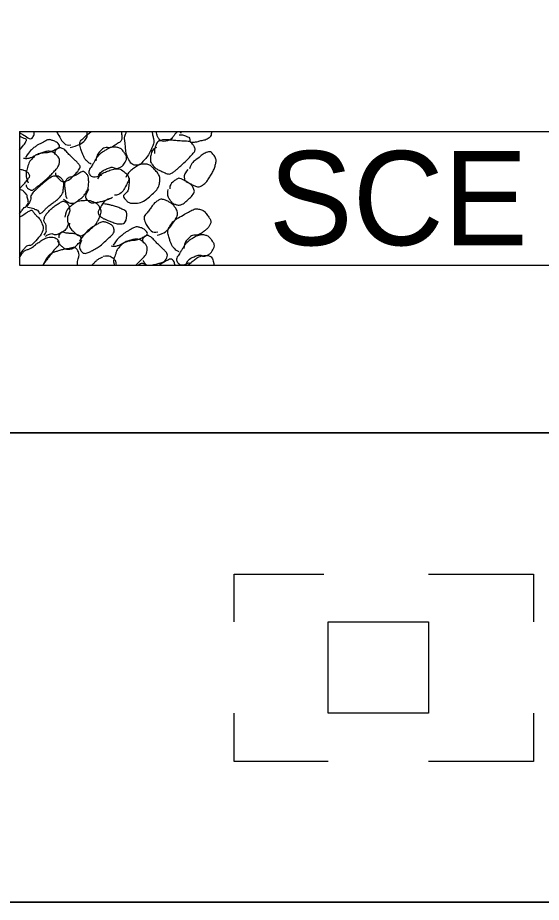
# Model space of a CAD drawing. Extents: x 1.3 to 34, y 0 to 22.5.
# Drawn here: x 11.694 to 12.252, y 7.825 to 8.767 of the extents above; entities that cross this region are included whole.
import ezdxf

# ---------------------------------------------------------------- set-up
doc = ezdxf.new("R2010")
doc.units = 0
for name, color, linetype in [('ANNO-SYMB', 7, 'Continuous'), ('ANNO-TABL', 7, 'Continuous'), ('USER-LINE', 7, 'Continuous')]:
    doc.layers.add(name, color=color, linetype=linetype)

msp = doc.modelspace()

# ---------------------------------------------------------------- linework, layer by layer
at = {"layer": 'ANNO-SYMB'}
for p, q in [((11.69643, 8.64567), (11.69641, 8.50339)), ((11.69643, 8.64567), (11.9385, 8.64567)), ((11.9385, 8.64567), (12.27755, 8.64567)), ((11.69641, 8.50339), (11.9385, 8.50338)), ((11.9385, 8.50338), (12.26197, 8.50339))]:
    msp.add_line(p, q, dxfattribs=at)
for points in [[(11.9252, 8.12358), (11.9252, 8.17447), (12.02037, 8.17447)], [(12.13208, 8.17447), (12.24378, 8.17447), (12.24378, 8.12358)], [(12.025, 7.97486), (11.9252, 7.97486), (11.9252, 8.02642)], [(12.24378, 8.02642), (12.24378, 7.97486), (12.13208, 7.97486)]]:
    msp.add_lwpolyline(points, dxfattribs=at)
msp.add_lwpolyline([(12.025, 8.12358), (12.13208, 8.12358), (12.13208, 8.02642), (12.025, 8.02642)], close=True, dxfattribs=at)
for points, degree in [([(11.69643, 8.64425), (11.6969, 8.64401), (11.69737, 8.64377), (11.69784, 8.64354), (11.70193, 8.64147), (11.7089, 8.63644), (11.71129, 8.6407), (11.71216, 8.64226), (11.7117, 8.64403), (11.71198, 8.64567)], 3), ([(11.69643, 8.62585), (11.6987, 8.62918), (11.70228, 8.63257), (11.7035, 8.63575), (11.70437, 8.63801), (11.69854, 8.63898), (11.69643, 8.64072)], 3), ([(11.70066, 8.61735), (11.70251, 8.61701), (11.7045, 8.6169), (11.70634, 8.61735), (11.70983, 8.61821), (11.71289, 8.62044), (11.71624, 8.62159), (11.72169, 8.62346), (11.72761, 8.62299), (11.73323, 8.62585), (11.73565, 8.62707), (11.7395, 8.62923), (11.7389, 8.6308), (11.73808, 8.63292), (11.73365, 8.63546), (11.7304, 8.63646), (11.72713, 8.63748), (11.72367, 8.63518), (11.7205, 8.63363), (11.71747, 8.63216), (11.71465, 8.63081), (11.712, 8.62868), (11.70822, 8.62563), (11.70516, 8.62224), (11.70279, 8.61806)], 3), ([(11.73605, 8.64567), (11.73597, 8.64545), (11.73593, 8.64519), (11.73607, 8.64496), (11.73989, 8.63849), (11.74502, 8.63009), (11.75092, 8.63151)], 3), ([(11.75023, 8.62868), (11.75818, 8.63028), (11.7686, 8.6362), (11.76863, 8.64423), (11.76863, 8.64471), (11.76863, 8.64518), (11.76863, 8.64566)], 3), ([(11.77287, 8.61097), (11.77092, 8.61183), (11.76939, 8.61288), (11.7679, 8.61452), (11.76536, 8.61732), (11.7641, 8.62047), (11.76297, 8.62373), (11.76151, 8.62792), (11.75967, 8.63402), (11.76295, 8.63716), (11.76614, 8.64021), (11.7695, 8.64288), (11.77285, 8.64567)], 3), ([(11.80472, 8.64566), (11.80483, 8.64329), (11.80576, 8.64092), (11.80542, 8.63857), (11.80489, 8.63494), (11.80075, 8.63295), (11.79765, 8.6308), (11.79316, 8.62769), (11.78686, 8.62936), (11.78278, 8.62515), (11.77976, 8.62205), (11.77824, 8.61838), (11.77782, 8.6145)], 3), ([(11.83727, 8.64566), (11.83783, 8.64379), (11.83825, 8.64191), (11.83869, 8.64001), (11.83908, 8.63837), (11.83936, 8.63669), (11.83941, 8.63504), (11.83947, 8.63261), (11.83832, 8.63031), (11.83727, 8.62797), (11.83459, 8.62198), (11.83093, 8.61681), (11.82665, 8.6124), (11.82375, 8.6094), (11.8162, 8.60981), (11.81391, 8.61381), (11.81052, 8.61975), (11.80953, 8.62587), (11.80898, 8.63221), (11.80869, 8.63551), (11.8078, 8.63903), (11.80898, 8.64213), (11.80943, 8.64332), (11.8099, 8.64449), (11.81037, 8.64567)], 3), ([(11.84222, 8.62868), (11.83787, 8.62703), (11.83616, 8.62087), (11.83584, 8.61664), (11.83569, 8.61455), (11.83638, 8.6123), (11.838, 8.61028), (11.84092, 8.60662), (11.84409, 8.60496), (11.84789, 8.6032), (11.85145, 8.60155), (11.85608, 8.59972), (11.85923, 8.60178), (11.86227, 8.60378), (11.86495, 8.60632), (11.86773, 8.60885), (11.87276, 8.61344), (11.87757, 8.61801), (11.88187, 8.623), (11.88371, 8.62512), (11.88307, 8.62908), (11.88116, 8.63149), (11.87979, 8.63322), (11.87824, 8.63487), (11.87621, 8.63506), (11.87267, 8.63539), (11.86912, 8.63545), (11.86559, 8.63575), (11.863, 8.63597), (11.8604, 8.63623), (11.85781, 8.63645), (11.85381, 8.63679), (11.84978, 8.6371), (11.84578, 8.63577), (11.8436, 8.63504), (11.84237, 8.63293), (11.84153, 8.63078), (11.84042, 8.62797), (11.83995, 8.62516), (11.8401, 8.62232)], 3), ([(11.86417, 8.64566), (11.86275, 8.64377), (11.86134, 8.64189), (11.85993, 8.64001), (11.8568, 8.63584), (11.84733, 8.63438), (11.84436, 8.63857), (11.8429, 8.64062), (11.84292, 8.64355), (11.84153, 8.64567)], 3), ([(11.86629, 8.64213), (11.86939, 8.64239), (11.87247, 8.64127), (11.87551, 8.64001), (11.87779, 8.63907), (11.87753, 8.63471), (11.87975, 8.63434), (11.88176, 8.63401), (11.88404, 8.6345), (11.88611, 8.63504), (11.89076, 8.63625), (11.89546, 8.63694), (11.89958, 8.64001), (11.90131, 8.6413), (11.90066, 8.6441), (11.9017, 8.64567)], 3), ([(11.867, 8.64566), (11.86747, 8.64518), (11.86795, 8.64471), (11.86842, 8.64423)], 2), ([(11.73464, 8.60178), (11.73432, 8.59952), (11.73633, 8.59731), (11.73819, 8.5954), (11.74265, 8.59083), (11.75064, 8.59487), (11.75516, 8.59964), (11.7583, 8.60294), (11.76196, 8.60806), (11.75942, 8.61097), (11.75711, 8.61363), (11.7544, 8.6162), (11.75162, 8.61877), (11.74809, 8.62205), (11.74455, 8.62662), (11.741, 8.62797), (11.73872, 8.62884), (11.73318, 8.62459), (11.73395, 8.62232)], 3), ([(11.78066, 8.59893), (11.78304, 8.60318), (11.78716, 8.605), (11.79127, 8.60672), (11.79504, 8.60829), (11.79955, 8.60553), (11.80331, 8.60744), (11.80581, 8.60872), (11.80761, 8.61072), (11.80898, 8.61311), (11.81043, 8.61564), (11.81067, 8.61901), (11.80898, 8.62159), (11.80677, 8.62495), (11.80391, 8.62796), (11.80048, 8.62868), (11.79617, 8.62958), (11.79113, 8.62768), (11.78703, 8.62515), (11.78465, 8.62368), (11.78253, 8.62226), (11.78066, 8.62017), (11.77829, 8.61754), (11.77674, 8.6146), (11.77499, 8.6117), (11.77284, 8.60813), (11.76906, 8.60286), (11.77146, 8.59966), (11.7739, 8.59641), (11.78052, 8.59766), (11.7842, 8.59966)], 3), ([(11.7035, 8.58903), (11.70328, 8.58718), (11.70524, 8.58507), (11.70703, 8.58409), (11.70994, 8.58249), (11.71361, 8.58561), (11.71624, 8.58764), (11.71892, 8.5897), (11.72147, 8.59175), (11.72403, 8.594), (11.72784, 8.59734), (11.73131, 8.60095), (11.73464, 8.60461), (11.73826, 8.60859), (11.73986, 8.61668), (11.73536, 8.62088), (11.73174, 8.62425), (11.72651, 8.62486), (11.7226, 8.62373), (11.71795, 8.62238), (11.71303, 8.62035), (11.70915, 8.61594), (11.70678, 8.61325), (11.70588, 8.61055), (11.70491, 8.60744), (11.70403, 8.60463), (11.70321, 8.60174), (11.7035, 8.59895), (11.70378, 8.59633), (11.70454, 8.59371), (11.70562, 8.59116)], 3), ([(11.87551, 8.60532), (11.87375, 8.60252), (11.87148, 8.59905), (11.87195, 8.59612), (11.87248, 8.59283), (11.87698, 8.59085), (11.88047, 8.58904), (11.88381, 8.58731), (11.88812, 8.58625), (11.89107, 8.58831), (11.89469, 8.59085), (11.89711, 8.59429), (11.89958, 8.59824), (11.90221, 8.60244), (11.90412, 8.60671), (11.90523, 8.61099), (11.9061, 8.61436), (11.90516, 8.61837), (11.90241, 8.62161), (11.89937, 8.62518), (11.89366, 8.62271), (11.89035, 8.62018), (11.88517, 8.61622), (11.87935, 8.61236), (11.87762, 8.60604)], 3), ([(11.8132, 8.59612), (11.81329, 8.59257), (11.81282, 8.58903), (11.81251, 8.58548), (11.81213, 8.58131), (11.80564, 8.57737), (11.80896, 8.57346), (11.81147, 8.57049), (11.81457, 8.56918), (11.81744, 8.5692), (11.82378, 8.56926), (11.83025, 8.57197), (11.83657, 8.5777), (11.84186, 8.58248), (11.84514, 8.58744), (11.84577, 8.59259), (11.84627, 8.59669), (11.84415, 8.60122), (11.84012, 8.60532), (11.83663, 8.60888), (11.83311, 8.61105), (11.82948, 8.61099), (11.82529, 8.61092), (11.8209, 8.60856), (11.81675, 8.60531), (11.81346, 8.60273), (11.81127, 8.60036), (11.80967, 8.59683)], 3), ([(11.69643, 8.5848), (11.69669, 8.58501), (11.6969, 8.58526), (11.69713, 8.5855), (11.70041, 8.58894), (11.70366, 8.59252), (11.70634, 8.59612), (11.70779, 8.59806), (11.7059, 8.60188), (11.7035, 8.60319), (11.70117, 8.60446), (11.69883, 8.60475), (11.69641, 8.60532)], 3), ([(11.74314, 8.57346), (11.7463, 8.57154), (11.74979, 8.5692), (11.75303, 8.56922), (11.75522, 8.56923), (11.75732, 8.57124), (11.75942, 8.57274), (11.76188, 8.5745), (11.76389, 8.57581), (11.76578, 8.57841), (11.76936, 8.58333), (11.77013, 8.58883), (11.77004, 8.59398), (11.77, 8.59641), (11.76945, 8.59898), (11.76721, 8.60107), (11.76382, 8.60421), (11.75944, 8.60054), (11.75588, 8.59895), (11.75205, 8.59724), (11.74783, 8.59664), (11.74524, 8.59259), (11.74391, 8.59049), (11.74431, 8.58832), (11.74456, 8.58621), (11.74505, 8.5822), (11.7454, 8.57815), (11.74667, 8.57419)], 3), ([(11.77993, 8.59542), (11.78231, 8.6), (11.78701, 8.60215), (11.79127, 8.60388), (11.79664, 8.60606), (11.80377, 8.60617), (11.80898, 8.60176), (11.81198, 8.59922), (11.81334, 8.59477), (11.81179, 8.59188), (11.80879, 8.58624), (11.804, 8.57781), (11.79765, 8.57771)], 3), ([(11.70491, 8.56498), (11.70832, 8.56484), (11.71188, 8.56334), (11.71482, 8.56213), (11.71639, 8.56148), (11.7177, 8.55774), (11.71907, 8.55858), (11.72169, 8.56018), (11.72421, 8.56354), (11.72686, 8.56567), (11.72864, 8.5671), (11.73066, 8.56846), (11.73252, 8.56993), (11.73594, 8.57264), (11.73904, 8.57511), (11.74172, 8.57914), (11.74291, 8.58094), (11.74296, 8.58289), (11.74314, 8.58479), (11.74346, 8.58805), (11.74415, 8.59145), (11.74172, 8.59471), (11.73995, 8.59707), (11.73766, 8.59809), (11.73536, 8.59824), (11.7335, 8.59835), (11.73136, 8.59794), (11.72969, 8.59683), (11.72767, 8.59548), (11.72585, 8.5941), (11.72403, 8.59259), (11.72014, 8.58936), (11.71643, 8.58613), (11.71271, 8.58267), (11.71097, 8.58104), (11.70952, 8.57917), (11.70846, 8.57702), (11.70803, 8.57616), (11.70875, 8.57508), (11.70846, 8.57419), (11.70746, 8.57119), (11.70614, 8.5684), (11.7042, 8.56569)], 3), ([(11.85428, 8.58409), (11.8538, 8.58083), (11.85372, 8.57746), (11.85569, 8.57417), (11.85766, 8.57087), (11.86058, 8.56851), (11.86347, 8.56779), (11.86721, 8.56687), (11.87172, 8.56932), (11.87551, 8.57276), (11.87947, 8.57635), (11.88337, 8.58127), (11.88186, 8.58479), (11.88029, 8.58842), (11.87563, 8.59145), (11.87126, 8.59398), (11.86882, 8.59539), (11.86582, 8.59628), (11.86347, 8.59469), (11.85982, 8.59221), (11.85637, 8.58872), (11.85638, 8.5848)], 3), ([(11.69643, 8.5579), (11.69763, 8.55954), (11.69876, 8.56122), (11.69994, 8.56286), (11.7013, 8.56474), (11.70365, 8.56575), (11.7049, 8.56779), (11.70616, 8.56986), (11.70547, 8.5726), (11.70491, 8.57488), (11.70449, 8.57661), (11.70431, 8.57823), (11.70279, 8.57982), (11.70072, 8.58197), (11.69858, 8.58383), (11.69641, 8.58336)], 3), ([(11.77004, 8.58407), (11.76846, 8.58064), (11.76525, 8.57616), (11.76863, 8.57276), (11.77128, 8.5701), (11.77423, 8.56946), (11.77711, 8.56993), (11.78159, 8.57066), (11.78613, 8.57177), (11.79056, 8.57347), (11.79228, 8.57414), (11.7939, 8.5748), (11.79553, 8.57559)], 3), ([(11.72262, 8.53525), (11.72541, 8.53826), (11.72476, 8.5414), (11.72474, 8.54444), (11.72472, 8.54704), (11.72193, 8.54964), (11.72262, 8.55222), (11.72362, 8.556), (11.72597, 8.55914), (11.72898, 8.56214), (11.73234, 8.5655), (11.73577, 8.56756), (11.7396, 8.56993), (11.7409, 8.57074), (11.74251, 8.57181), (11.74385, 8.57134), (11.74657, 8.57039), (11.74887, 8.56724), (11.74952, 8.56426), (11.75044, 8.56002), (11.74748, 8.55578), (11.7474, 8.55153), (11.74736, 8.54988), (11.74856, 8.54821), (11.74808, 8.54656), (11.74672, 8.54195), (11.74265, 8.53879), (11.73819, 8.53665), (11.73479, 8.53503), (11.73092, 8.53714), (11.72757, 8.53594), (11.72627, 8.53548), (11.72507, 8.53501), (11.72401, 8.53384)], 3), ([(11.7495, 8.54798), (11.74876, 8.54419), (11.75241, 8.54031), (11.75586, 8.53737), (11.76105, 8.53293), (11.76857, 8.53869), (11.77358, 8.54303), (11.77629, 8.54537), (11.7783, 8.54781), (11.77994, 8.55082), (11.78238, 8.55528), (11.7841, 8.56136), (11.78135, 8.56569), (11.77987, 8.56803), (11.77762, 8.56954), (11.77499, 8.57064), (11.77218, 8.57182), (11.7693, 8.57218), (11.76649, 8.57205), (11.76191, 8.57183), (11.75742, 8.57115), (11.75304, 8.56781), (11.7481, 8.56404), (11.74542, 8.5596), (11.74455, 8.55434)], 3), ([(11.7941, 8.57417), (11.78862, 8.57405), (11.78434, 8.56776), (11.78135, 8.56286), (11.77996, 8.56057), (11.78053, 8.55677), (11.78276, 8.55506), (11.78543, 8.553), (11.78832, 8.55203), (11.79127, 8.5508), (11.79558, 8.549), (11.80046, 8.54711), (11.80472, 8.54727), (11.80936, 8.54744), (11.81196, 8.55998), (11.80755, 8.56213), (11.80338, 8.56417), (11.79881, 8.56592), (11.7941, 8.56708), (11.79127, 8.56778), (11.78842, 8.5684), (11.78559, 8.5685)], 3), ([(11.84293, 8.53525), (11.8512, 8.5371), (11.85718, 8.54417), (11.86206, 8.55153), (11.86468, 8.55547), (11.86475, 8.56112), (11.86206, 8.56498), (11.86006, 8.56786), (11.8574, 8.56982), (11.85428, 8.57134), (11.85097, 8.57295), (11.84665, 8.57401), (11.84366, 8.57203), (11.84015, 8.56971), (11.83778, 8.56643), (11.83515, 8.56284), (11.83249, 8.55922), (11.82834, 8.55518), (11.8295, 8.55153), (11.83124, 8.54603), (11.83798, 8.53685), (11.84365, 8.53877)], 3), ([(11.69641, 8.55436), (11.7002, 8.55668), (11.70397, 8.55934), (11.70774, 8.56143), (11.70974, 8.56254), (11.71153, 8.55905), (11.71339, 8.55718), (11.71659, 8.55394), (11.71938, 8.5507), (11.7205, 8.54729), (11.72264, 8.54072), (11.71685, 8.53234), (11.71056, 8.52605), (11.70826, 8.52376), (11.70468, 8.52458), (11.70278, 8.52249), (11.70054, 8.52004), (11.69862, 8.51719), (11.69641, 8.51472)], 3), ([(11.8663, 8.51756), (11.86436, 8.51841), (11.86282, 8.51945), (11.86134, 8.52108), (11.85879, 8.52388), (11.85754, 8.52704), (11.8564, 8.53029), (11.85485, 8.5347), (11.8537, 8.5402), (11.85638, 8.54445), (11.86068, 8.55126), (11.86713, 8.5546), (11.87409, 8.55858), (11.87863, 8.56119), (11.88373, 8.56372), (11.88825, 8.56286), (11.89224, 8.5621), (11.89545, 8.55833), (11.89816, 8.55434), (11.89992, 8.55175), (11.90032, 8.54826), (11.89885, 8.54586), (11.89695, 8.54276), (11.89415, 8.54026), (11.89108, 8.53808), (11.88657, 8.53487), (11.88035, 8.53596), (11.87621, 8.5317), (11.87321, 8.52861), (11.87168, 8.52495), (11.87126, 8.52108)], 3), ([(11.76225, 8.52956), (11.76085, 8.52613), (11.75961, 8.5215), (11.76225, 8.51827), (11.76474, 8.51523), (11.76985, 8.51664), (11.77287, 8.51827), (11.77779, 8.52092), (11.78247, 8.52381), (11.78702, 8.52817), (11.79157, 8.53254), (11.79785, 8.53785), (11.79694, 8.54232), (11.79641, 8.54492), (11.79236, 8.54746), (11.78915, 8.54868), (11.7857, 8.54999), (11.78176, 8.54838), (11.77854, 8.54656), (11.77491, 8.54451), (11.77156, 8.54248), (11.76863, 8.5395), (11.76535, 8.53617), (11.76257, 8.53279), (11.76013, 8.52887)], 3), ([(11.7941, 8.5239), (11.79596, 8.5236), (11.79793, 8.52346), (11.79977, 8.5239), (11.80327, 8.52475), (11.80633, 8.527), (11.80967, 8.52817), (11.8151, 8.53007), (11.82104, 8.52964), (11.82665, 8.53241), (11.82922, 8.53368), (11.8332, 8.53634), (11.83233, 8.53808), (11.83123, 8.54029), (11.82707, 8.54283), (11.82384, 8.54373), (11.82057, 8.54463), (11.81704, 8.54263), (11.81393, 8.54091), (11.81084, 8.53921), (11.80807, 8.53757), (11.80543, 8.53525), (11.80181, 8.53205), (11.79863, 8.52878), (11.79623, 8.52463)], 3), ([(11.69643, 8.51118), (11.6977, 8.51343), (11.69882, 8.51569), (11.70067, 8.51754), (11.70297, 8.51984), (11.70658, 8.52003), (11.70917, 8.52178), (11.71137, 8.52327), (11.71321, 8.52518), (11.71555, 8.52675), (11.72021, 8.52988), (11.72549, 8.53304), (11.7304, 8.53311), (11.73321, 8.53315), (11.73759, 8.53073), (11.73819, 8.52816), (11.73899, 8.5247), (11.73427, 8.52086), (11.73179, 8.51756), (11.72826, 8.51284), (11.72473, 8.50812), (11.72119, 8.50339)], 3), ([(11.73678, 8.52958), (11.73801, 8.52702), (11.7394, 8.52516), (11.74172, 8.52322), (11.74392, 8.52138), (11.74649, 8.52018), (11.7488, 8.52037), (11.75314, 8.52073), (11.75732, 8.52446), (11.76083, 8.52817), (11.76259, 8.53004), (11.76176, 8.53427), (11.75942, 8.53525), (11.75546, 8.5369), (11.75144, 8.53699), (11.7474, 8.53737), (11.74505, 8.53758), (11.74264, 8.5391), (11.74031, 8.53735), (11.73854, 8.53602), (11.73798, 8.53412), (11.73819, 8.5324)], 3), ([(11.83729, 8.50338), (11.84083, 8.5043), (11.84437, 8.5051), (11.8479, 8.50621), (11.85179, 8.50744), (11.85482, 8.51467), (11.85214, 8.51756), (11.84971, 8.52018), (11.84705, 8.52276), (11.84436, 8.52534), (11.84106, 8.5285), (11.83776, 8.53246), (11.83445, 8.53452), (11.83224, 8.5359), (11.82639, 8.53116), (11.82736, 8.52889)], 3), ([(11.87409, 8.5055), (11.87645, 8.50974), (11.88059, 8.51156), (11.88469, 8.51328), (11.88846, 8.51486), (11.89298, 8.51209), (11.89675, 8.51401), (11.89925, 8.51529), (11.90104, 8.51729), (11.90241, 8.51968), (11.90386, 8.52221), (11.90411, 8.52559), (11.90241, 8.52817), (11.90019, 8.53153), (11.89733, 8.53455), (11.8939, 8.53525), (11.88959, 8.53613), (11.88455, 8.53421), (11.88045, 8.53168), (11.87807, 8.53022), (11.87596, 8.52881), (11.87409, 8.52673), (11.87171, 8.5241), (11.87016, 8.52116), (11.86841, 8.51825), (11.86626, 8.51468), (11.86249, 8.50942), (11.8649, 8.50623), (11.86733, 8.50298), (11.87393, 8.50426), (11.87762, 8.50623)], 3), ([(11.82029, 8.50339), (11.82289, 8.50599), (11.82548, 8.50858), (11.82808, 8.51118), (11.83191, 8.51502), (11.83329, 8.52325), (11.82879, 8.52744), (11.82518, 8.53081), (11.81996, 8.53143), (11.81605, 8.53029), (11.8114, 8.52894), (11.80649, 8.5269), (11.8026, 8.52251), (11.80022, 8.51982), (11.79933, 8.51711), (11.79833, 8.51401), (11.79742, 8.5112), (11.79631, 8.50824), (11.79694, 8.5055), (11.7971, 8.50479), (11.79745, 8.5041), (11.79765, 8.50339)], 3), ([(11.75801, 8.50339), (11.75796, 8.50906), (11.76142, 8.51473), (11.7573, 8.52037), (11.7554, 8.52297), (11.75205, 8.52149), (11.7495, 8.52108), (11.74525, 8.52042), (11.741, 8.51965), (11.73678, 8.51827), (11.7337, 8.51726), (11.73066, 8.51638), (11.72828, 8.51401), (11.72509, 8.51083), (11.72345, 8.50712), (11.72119, 8.50339)], 3), ([(11.7849, 8.51187), (11.78235, 8.51075), (11.77992, 8.50943), (11.77781, 8.50762), (11.77628, 8.50631), (11.77506, 8.50472), (11.77358, 8.50339)], 3), ([(11.79977, 8.50338), (11.79926, 8.50565), (11.79917, 8.50785), (11.79694, 8.50975), (11.79319, 8.51294), (11.78935, 8.51336), (11.78559, 8.5126)], 3), ([(11.83162, 8.50338), (11.83068, 8.50389), (11.82975, 8.50443), (11.82879, 8.5048), (11.82703, 8.50548), (11.82481, 8.5045), (11.82312, 8.50339)], 3), ([(11.82806, 8.50835), (11.82864, 8.50666), (11.83002, 8.50505), (11.83091, 8.50339)], 2), ([(11.86206, 8.50339), (11.8615, 8.50474), (11.8616, 8.50644), (11.86064, 8.50763), (11.85801, 8.5109), (11.8521, 8.50759), (11.8486, 8.50551), (11.84742, 8.50482), (11.84624, 8.50411), (11.84507, 8.50338)], 3), ([(11.87551, 8.50339), (11.87861, 8.5056), (11.8816, 8.5083), (11.88471, 8.51047), (11.88949, 8.51379), (11.90074, 8.51404), (11.90241, 8.50833), (11.90289, 8.50668), (11.90335, 8.50503), (11.90382, 8.50338)], 3)]:
    msp.add_open_spline(points, degree=degree, dxfattribs=at)
at = {"layer": 'ANNO-TABL'}
for p, q in [((2, 8.325), (18.2, 8.325)), ((2, 7.825), (18.2, 7.825))]:
    msp.add_line(p, q, dxfattribs=at)
msp.add_lwpolyline([(7.4, 7.825), (12.8, 7.825), (12.8, 19.825), (7.4, 19.825)], close=True, dxfattribs=at)
at = {"layer": 'USER-LINE'}
for p, q in [((12.75, 8.325), (11.4, 8.325)), ((12.75, 8.325), (11.4, 8.325)), ((12.75, 7.825), (11.4, 7.825))]:
    msp.add_line(p, q, dxfattribs=at)

# ---------------------------------------------------------------- texts
at = {"layer": 'ANNO-SYMB'}
msp.add_text('SCE', height=0.100301, dxfattribs=at).set_placement((11.96184, 8.52461))

doc.saveas('drawing.dxf')
